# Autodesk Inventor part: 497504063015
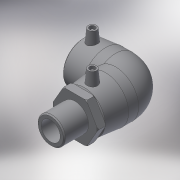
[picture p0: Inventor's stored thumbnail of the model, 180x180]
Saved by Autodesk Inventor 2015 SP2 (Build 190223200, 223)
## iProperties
Created: 2017-06
Part Number: 497504063015
Material: Generic
Description: PE Male Transition Elbow 90° 63x  1 1_2
Document SubType Name: Modeling
Designer: KIM
Mass: 612.754 g
Surface Area: 1051.6 cm^2
Volume: 612.754 cm^3
Density: 1 g/cm^3
Appearance: Default
Author: KIM
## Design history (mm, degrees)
derived "497504.ipt"
feature "Solid1::497504.ipt"
feature "Solid2::497504.ipt"
tag "TaggingFeature1"
workplane "Work Plane2"
body "Solid1"
body "Solid2"
other parameters: "d2" = 81, "d4" = 39.33333, "d5" = 72.9, "d8" = 168 deg, "d10" = 22.8, "d11" = 7.6, "d29" = 59, "d30" = 15, "d31" = 61.36, "d34" = 5 deg, "d41" = 4, "d42" = 14, "d43" = 0, "d48" = 77.5, "d49" = 63, "d50" = 6.3, "d51" = 22.8, "d52" = 57, "d54" = 90 deg, "d86" = 3, "d87" = 0, "d93" = 0.1, "d94" = 14.25, "d95" = 47.803, "d96" = 33.4621, "d97" = 48, "d98" = 57, "d99" = 81, "d100" = 51.3, "d102" = 1.89, "d106" = 0, "d108" = 51.3, "d114" = 57, "d115" = 0, "d116" = -57, "d_" = 63, "L_" = 175, "L_1" = 57, "D_" = 48, "A_" = 59, "d_2" = 12, "L_2" = 57, "D_1" = 81, "R_" = 47.803
